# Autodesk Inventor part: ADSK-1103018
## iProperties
Shininess: 50.0
Length Units: 11272
Angle Units: 11279
Time Units: 11290
Mass Units: 11286
Length Display Precision: 4
Angle Display Precision: 2
Compacted: True
Created: 2000-09
Part Number: ADSK-1103018
Document SubType Name: Modeling
Description: INTAKE BODY
Mass: 1.50386 g
Surface Area: 7.7204 cm^2
Volume: 0.554931 cm^3
Density: 2.71 g/cm^3
Material: Aluminum-6061
Density: 0.0
Volumn: 0.0
Area: 0.0
PropertySet Name: Model Information
Control State: 0
Master: False
Checked Out: False
Author: Autodesk, Inc.
